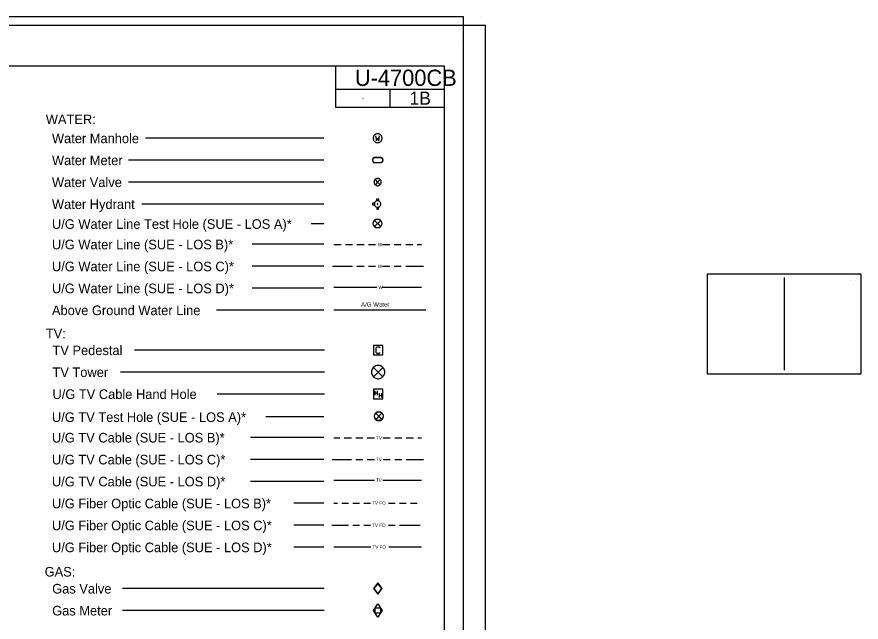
# Model space of a CAD drawing. Extents: x 811137 to 813186, y 647386 to 648494.
# Drawn here: x 812410 to 813186, y 647937 to 648494 of the extents above; entities that cross this region are included whole.
import ezdxf

# ---------------------------------------------------------------- set-up
doc = ezdxf.new("R2010")
doc.units = 0
for name, color, linetype in [('Default', 7, 'Continuous'), ('Exist Utilities TV Test Hole SUE LOS A CELL', 7, 'Continuous'), ('Exist Utilities Water Test Hole SUE LOS A CELL', 7, 'Continuous'), ('Sheet_Plan', 7, 'Continuous'), ('Sheet_Symbology', 7, 'Continuous'), ('Sheet_Title_Block_Text', 7, 'Continuous'), ('z - Construction', 7, 'Continuous')]:
    doc.layers.add(name, color=color, linetype=linetype)

msp = doc.modelspace()

# ---------------------------------------------------------------- linework, layer by layer
at = {"layer": 'Default'}
for p, q in [((812836.63, 648494.02), (812836.63, 648494.02)), ((812836.63, 648494.02), (812836.63, 648494.02)), ((812836.63, 648494.02), (812836.63, 648494.02)), ((812815.58, 648471.57), (812815.58, 648471.57)), ((812815.58, 648471.57), (812815.58, 648471.57)), ((812815.58, 648471.57), (812815.58, 648471.57))]:
    msp.add_line(p, q, dxfattribs=at)
msp.add_lwpolyline([(812820.63, 648494.02), (811136.63, 648494.02), (811136.63, 647394.02), (812820.63, 647394.02)], close=True, dxfattribs=at)
at = {"layer": 'Exist Utilities TV Test Hole SUE LOS A CELL'}
for points in [[(812745.62, 648129.54), (812739.92, 648123.83), (812742.77, 648126.69), (812739.92, 648129.54), (812745.62, 648123.83)], [(812739.92, 648129.54), (812742.77, 648126.69), (812745.62, 648129.54)], [(812745.62, 648123.83), (812742.77, 648126.69), (812739.92, 648123.83)]]:
    msp.add_lwpolyline(points, dxfattribs=at)
msp.add_circle((812742.77, 648126.69), 4.03, dxfattribs=at)
for start, end in [(45, 135), (225, 315)]:
    msp.add_arc((812742.77, 648126.69), 4.03, start, end, dxfattribs=at)
at = {"layer": 'Exist Utilities Water Test Hole SUE LOS A CELL'}
for points in [[(812744.47, 648306.86), (812738.77, 648301.15), (812741.62, 648304), (812738.77, 648306.86), (812744.47, 648301.15)], [(812738.77, 648306.86), (812741.62, 648304), (812744.47, 648306.86)], [(812744.47, 648301.15), (812741.62, 648304), (812738.77, 648301.15)]]:
    msp.add_lwpolyline(points, dxfattribs=at)
msp.add_circle((812741.62, 648304), 4.03, dxfattribs=at)
for start, end in [(45, 135), (225, 315)]:
    msp.add_arc((812741.62, 648304), 4.03, start, end, dxfattribs=at)
at = {"layer": 'Sheet_Plan'}
for p, q in [((812803.27, 648448.58), (811178.27, 648448.58)), ((812703.28, 648410.66), (812703.28, 648448.58)), ((812803.25, 647423.58), (812803.27, 648448.58)), ((812803.27, 648427.16), (812703.28, 648427.16)), ((812753.27, 648410.66), (812753.28, 648427.16)), ((812803.27, 648410.66), (812703.28, 648410.66))]:
    msp.add_line(p, q, dxfattribs=at)
msp.add_circle((812703.28, 648410.66), 0.06, dxfattribs=at)
at = {"layer": 'Sheet_Symbology'}
for p, q in [((812692.2, 648382.43), (812528.37, 648382.43)), ((812692.2, 648362.25), (812512.58, 648362.25)), ((812738.58, 648364.85), (812744.77, 648364.85)), ((812738.58, 648364.65), (812744.77, 648364.65)), ((812744.73, 648359.91), (812738.58, 648359.91)), ((812744.73, 648359.7), (812738.58, 648359.7)), ((812692.2, 648342.08), (812512.58, 648342.08)), ((812692.2, 648321.9), (812524.94, 648321.9)), ((812692.2, 648303.65), (812680.55, 648303.65)), ((812692.2, 648284.84), (812626.24, 648284.84)), ((812701.46, 648284.62), (812708.02, 648284.62)), ((812712.06, 648284.62), (812718.61, 648284.62)), ((812722.65, 648284.62), (812729.21, 648284.62)), ((812733.24, 648284.62), (812739.8, 648284.62)), ((812746.26, 648284.62), (812752.82, 648284.62)), ((812756.85, 648284.62), (812763.41, 648284.62)), ((812767.45, 648284.62), (812774, 648284.62)), ((812778.04, 648284.62), (812782.01, 648284.62)), ((812692.2, 648264.66), (812626.24, 648264.66)), ((812700.32, 648264.66), (812718.61, 648264.66)), ((812722.65, 648264.66), (812729.21, 648264.66)), ((812733.24, 648264.66), (812739.8, 648264.66)), ((812746.26, 648264.66), (812752.82, 648264.66)), ((812756.85, 648264.66), (812763.41, 648264.66)), ((812767.45, 648264.66), (812783.9, 648264.66)), ((812692.2, 648244.48), (812626.24, 648244.48)), ((812701.3, 648245.36), (812740.95, 648245.36)), ((812745.99, 648245.36), (812782.01, 648245.36)), ((812692.2, 648224.3), (812593.62, 648224.3)), ((812701.3, 648224.52), (812786.06, 648224.52)), ((812692.69, 648187.53), (812518.23, 648187.53)), ((812741.5, 648184.56), (812742.8, 648184.56)), ((812692.69, 648167.35), (812505.18, 648167.35)), ((812739.04, 648150.23), (812739.04, 648146.16)), ((812739.04, 648148.15), (812741.37, 648148.15)), ((812741.37, 648150.23), (812741.37, 648146.16)), ((812742.93, 648148.01), (812742.93, 648143.95)), ((812745.25, 648148.01), (812745.25, 648143.95)), ((812692.69, 648147.17), (812594.1, 648147.17)), ((812742.93, 648145.94), (812745.25, 648145.94)), ((812692.2, 648126.05), (812638.87, 648126.05)), ((812692.2, 648107.17), (812624.92, 648107.17)), ((812701.3, 648106.84), (812706.92, 648106.84)), ((812710.96, 648106.84), (812717.52, 648106.84)), ((812721.55, 648106.84), (812728.11, 648106.84)), ((812732.15, 648106.84), (812738.7, 648106.84)), ((812746.78, 648106.84), (812753.33, 648106.84)), ((812757.37, 648106.84), (812763.93, 648106.84)), ((812767.96, 648106.84), (812774.52, 648106.84)), ((812778.56, 648106.84), (812782.01, 648106.84)), ((812692.2, 648086.99), (812624.92, 648086.99)), ((812699.9, 648086.99), (812717.52, 648086.99)), ((812721.55, 648086.99), (812728.11, 648086.99)), ((812732.15, 648086.99), (812738.7, 648086.99)), ((812746.78, 648086.99), (812753.33, 648086.99)), ((812757.37, 648086.99), (812763.93, 648086.99)), ((812767.96, 648086.99), (812783.71, 648086.99)), ((812692.2, 648066.81), (812624.92, 648066.81)), ((812701.3, 648068.03), (812738.8, 648068.03)), ((812746.37, 648068.03), (812782.01, 648068.03)), ((812692.2, 648046.63), (812664.72, 648046.63)), ((812701.3, 648046.88), (812704.83, 648046.88)), ((812708.86, 648046.88), (812714.92, 648046.88)), ((812718.95, 648046.88), (812725.01, 648046.88)), ((812729.04, 648046.88), (812735.1, 648046.88)), ((812751.74, 648046.88), (812757.8, 648046.88)), ((812761.83, 648046.88), (812767.89, 648046.88)), ((812771.92, 648046.88), (812777.98, 648046.88)), ((812692.2, 648026.45), (812664.72, 648026.45)), ((812699.64, 648026.45), (812714.92, 648026.45)), ((812718.95, 648026.45), (812725.01, 648026.45)), ((812729.04, 648026.45), (812735.1, 648026.45)), ((812751.74, 648026.45), (812757.8, 648026.45)), ((812761.83, 648026.45), (812780.73, 648026.45)), ((812692.2, 648006.28), (812664.72, 648006.28)), ((812701.3, 648006.51), (812735.39, 648006.51)), ((812752.03, 648006.51), (812782.01, 648006.51)), ((812741.86, 647973.03), (812738.32, 647968.27)), ((812745.41, 647968.27), (812741.86, 647973.03)), ((812692.41, 647968.27), (812507.28, 647968.27)), ((812738.32, 647968.27), (812741.86, 647963.51)), ((812741.86, 647963.51), (812745.41, 647968.27)), ((812692.41, 647948.09), (812507.28, 647948.09))]:
    msp.add_line(p, q, dxfattribs=at)
for points in [[(812741.66, 648386.53), (812741.13, 648386.5), (812740.64, 648386.4), (812740.15, 648386.23), (812739.69, 648386.01), (812739.26, 648385.74), (812738.87, 648385.42), (812738.51, 648385.02), (812738.21, 648384.63), (812737.95, 648384.17), (812737.79, 648383.68), (812737.66, 648383.19), (812737.59, 648382.7), (812737.59, 648382.17), (812737.66, 648381.68), (812737.79, 648381.16), (812737.95, 648380.7), (812738.21, 648380.24), (812738.51, 648379.84), (812738.87, 648379.45), (812739.26, 648379.12), (812739.69, 648378.86), (812740.15, 648378.63), (812740.64, 648378.47), (812741.16, 648378.37), (812741.66, 648378.34), (812742.18, 648378.37), (812742.67, 648378.47), (812743.16, 648378.63), (812743.62, 648378.86), (812744.05, 648379.12), (812744.44, 648379.45), (812744.8, 648379.84), (812745.1, 648380.24), (812745.36, 648380.7), (812745.52, 648381.19), (812745.65, 648381.68), (812745.72, 648382.17), (812745.72, 648382.7), (812745.65, 648383.19), (812745.52, 648383.71), (812745.36, 648384.17), (812745.1, 648384.63), (812744.8, 648385.02), (812744.44, 648385.42), (812744.05, 648385.74), (812743.62, 648386.01), (812743.16, 648386.23), (812742.67, 648386.4), (812742.15, 648386.5), (812741.66, 648386.53)], [(812739.82, 648384.7), (812740.67, 648379.91), (812741.66, 648382.93), (812742.67, 648379.91), (812743.52, 648384.7)], [(812738.58, 648364.85), (812738.17, 648364.65), (812737.81, 648364.36), (812737.48, 648364), (812737.24, 648363.63), (812737.04, 648363.19), (812736.92, 648362.74), (812736.87, 648362.3), (812736.92, 648361.81), (812737.04, 648361.36), (812737.24, 648360.96), (812737.48, 648360.55), (812737.81, 648360.23), (812738.17, 648359.95), (812738.58, 648359.7)], [(812738.66, 648364.69), (812738.25, 648364.44), (812737.89, 648364.16), (812737.56, 648363.8), (812737.32, 648363.43), (812737.16, 648362.98), (812737.08, 648362.5), (812737.08, 648362.05), (812737.16, 648361.61), (812737.32, 648361.16), (812737.56, 648360.75), (812737.89, 648360.39), (812738.25, 648360.11), (812738.66, 648359.91)], [(812744.65, 648364.69), (812745.1, 648364.48), (812745.46, 648364.16), (812745.75, 648363.83), (812745.99, 648363.43), (812746.15, 648362.98), (812746.23, 648362.5), (812746.23, 648362.05), (812746.15, 648361.57), (812745.99, 648361.16), (812745.75, 648360.75), (812745.42, 648360.39), (812745.06, 648360.11), (812744.65, 648359.86)], [(812744.73, 648364.85), (812745.14, 648364.65), (812745.5, 648364.36), (812745.83, 648364), (812746.07, 648363.63), (812746.27, 648363.19), (812746.4, 648362.74), (812746.44, 648362.3), (812746.4, 648361.81), (812746.27, 648361.36), (812746.07, 648360.96), (812745.83, 648360.55), (812745.5, 648360.23), (812745.14, 648359.95), (812744.73, 648359.7)], [(812745.01, 648342.08), (812744.97, 648342.56), (812744.86, 648343.08), (812744.67, 648343.53), (812744.41, 648343.98), (812744.11, 648344.35), (812743.74, 648344.68), (812743.33, 648344.98), (812742.88, 648345.2), (812742.4, 648345.35), (812741.92, 648345.43), (812741.39, 648345.43), (812740.91, 648345.35), (812740.43, 648345.2), (812739.98, 648344.98), (812739.57, 648344.68), (812739.2, 648344.35), (812738.9, 648343.98), (812738.64, 648343.53), (812738.45, 648343.08), (812738.34, 648342.56), (812738.3, 648342.08), (812738.34, 648341.59), (812738.45, 648341.07), (812738.64, 648340.62), (812738.9, 648340.18), (812739.2, 648339.8), (812739.57, 648339.47), (812739.98, 648339.17), (812740.43, 648338.95), (812740.91, 648338.8), (812741.39, 648338.73), (812741.92, 648338.73), (812742.4, 648338.8), (812742.88, 648338.95), (812743.33, 648339.17), (812743.74, 648339.47), (812744.11, 648339.8), (812744.41, 648340.18), (812744.67, 648340.62), (812744.86, 648341.07), (812744.97, 648341.59), (812745.01, 648342.08)], [(812744.04, 648339.69), (812739.27, 648344.46), (812741.66, 648342.08), (812739.27, 648339.69), (812744.04, 648344.46)], [(812740.92, 648324.8), (812740.92, 648326.74), (812742.47, 648326.74), (812742.47, 648324.76)], [(812738.79, 648322.67), (812736.85, 648322.67), (812736.85, 648321.12), (812738.79, 648321.12)], [(812741.62, 648324.88), (812741.15, 648324.84), (812740.69, 648324.72), (812740.22, 648324.53), (812739.83, 648324.26), (812739.49, 648323.95), (812739.18, 648323.56), (812738.94, 648323.14), (812738.79, 648322.67), (812738.67, 648322.21), (812738.67, 648321.74), (812738.75, 648321.28), (812738.87, 648320.81), (812739.1, 648320.39), (812739.37, 648320), (812739.72, 648319.65), (812740.11, 648319.34), (812740.53, 648319.15), (812741, 648318.99), (812741.46, 648318.92), (812741.93, 648318.92), (812742.39, 648318.99), (812742.85, 648319.19), (812743.28, 648319.38), (812743.67, 648319.69), (812743.98, 648320.04), (812744.25, 648320.43), (812744.44, 648320.89), (812744.6, 648321.36), (812744.64, 648321.82), (812744.6, 648322.29), (812744.52, 648322.75), (812744.33, 648323.21), (812744.1, 648323.64), (812743.79, 648323.99), (812743.4, 648324.3), (812743.01, 648324.57), (812742.55, 648324.72), (812742.08, 648324.84), (812741.62, 648324.88)], [(812740.92, 648318.99), (812740.92, 648317.06), (812742.47, 648317.06), (812742.47, 648319.03)], [(812741.66, 648322.25), (812741.5, 648322.21), (812741.38, 648322.09), (812741.31, 648321.94), (812741.35, 648321.78), (812741.42, 648321.63), (812741.58, 648321.55), (812741.73, 648321.55), (812741.89, 648321.63), (812741.96, 648321.78), (812742, 648321.94), (812741.93, 648322.09), (812741.81, 648322.21), (812741.66, 648322.25)], [(812737.93, 648183.33), (812746.34, 648183.33), (812746.34, 648191.74), (812737.93, 648191.74), (812737.93, 648183.33)], [(812744.11, 648185.49), (812743.11, 648184.56), (812741.17, 648184.56), (812740.24, 648185.49), (812740.24, 648189.57), (812741.17, 648190.5), (812743.11, 648190.5), (812744.11, 648189.57)], [(812748.21, 648167.35), (812748.15, 648168.23), (812747.95, 648169.18), (812747.61, 648169.98), (812747.13, 648170.8), (812746.59, 648171.47), (812745.92, 648172.08), (812745.18, 648172.62), (812744.37, 648173.02), (812743.49, 648173.3), (812742.61, 648173.43), (812741.66, 648173.43), (812740.79, 648173.3), (812739.91, 648173.02), (812739.1, 648172.62), (812738.36, 648172.08), (812737.68, 648171.47), (812737.14, 648170.8), (812736.67, 648169.98), (812736.33, 648169.18), (812736.13, 648168.23), (812736.06, 648167.35), (812736.13, 648166.47), (812736.33, 648165.53), (812736.67, 648164.72), (812737.14, 648163.91), (812737.68, 648163.23), (812738.36, 648162.62), (812739.1, 648162.08), (812739.91, 648161.68), (812740.79, 648161.41), (812741.66, 648161.28), (812742.61, 648161.28), (812743.49, 648161.41), (812744.37, 648161.68), (812745.18, 648162.08), (812745.92, 648162.62), (812746.59, 648163.23), (812747.13, 648163.91), (812747.61, 648164.72), (812747.95, 648165.53), (812748.15, 648166.47), (812748.21, 648167.35)], [(812746.46, 648163.03), (812737.82, 648171.67), (812742.14, 648167.35), (812737.82, 648163.03), (812746.46, 648171.67)], [(812737.79, 648142.83), (812746.48, 648142.83), (812746.48, 648151.52), (812737.79, 648151.52), (812737.79, 648142.83)], [(812741.86, 647973.44), (812738.01, 647968.27), (812741.86, 647963.1), (812745.71, 647968.27), (812741.86, 647973.44)], [(812738.01, 647948.09), (812741.86, 647954.32), (812745.71, 647948.09), (812741.86, 647941.86), (812738.01, 647948.09)], [(812739.48, 647950.42), (812744.24, 647950.42), (812744.24, 647945.71), (812739.48, 647945.71), (812739.48, 647950.42)]]:
    msp.add_lwpolyline(points, dxfattribs=at)
at = {"layer": 'z - Construction'}
for p, q in [((812840.77, 648486.08), (811140.78, 648486.08)), ((812840.77, 647386.08), (812840.77, 648486.08)), ((813186.12, 648257.54), (813044.46, 648257.54)), ((813044.46, 648257.54), (813044.46, 648165.88)), ((813186.12, 648165.88), (813186.12, 648257.54)), ((813115.29, 648254.42), (813115.29, 648169)), ((813044.46, 648165.88), (813186.12, 648165.88))]:
    msp.add_line(p, q, dxfattribs=at)
for centre, radius in [((812753.28, 648437.87), 0.06), ((812728.28, 648418.91), 0.06), ((812778.27, 648418.91), 0.06), ((813176.75, 648251.95), 0.005), ((813178.83, 648253.53), 0.005), ((813180.92, 648251.95), 0.005)]:
    msp.add_circle(centre, radius, dxfattribs=at)

# ---------------------------------------------------------------- texts
at = {"layer": 'Sheet_Symbology'}
for s, height, p in [('WATER:', 8.828, (812436.67, 648395.39)), ('Water Manhole', 8.8282, (812442.29, 648377.86)), ('Water Meter', 8.8282, (812442.29, 648357.68)), ('Water Valve', 8.8282, (812442.29, 648337.5)), ('Water Hydrant', 8.8282, (812442.29, 648317.32)), ('U/G Water Line Test Hole (SUE - LOS A)*', 8.8282, (812442.29, 648299.07)), ('U/G Water Line (SUE - LOS B)*', 8.8282, (812442.29, 648280.26)), ('W', 3.03, (812741.92, 648283.1)), ('U/G Water Line (SUE - LOS C)*', 8.8282, (812442.29, 648260.08)), ('W', 3.03, (812741.92, 648263.14)), ('U/G Water Line (SUE - LOS D)*', 8.8282, (812442.29, 648239.9)), ('W', 3.03, (812742.36, 648243.85)), ('Above Ground Water Line', 8.8282, (812442.29, 648219.72)), ('A/G Water', 4.036, (812726.45, 648227.54)), ('TV:', 8.828, (812436.67, 648198.37)), ('TV Pedestal', 8.8282, (812442.77, 648182.95)), ('TV Tower', 8.828, (812442.77, 648162.77)), ('U/G TV Cable Hand Hole', 8.8282, (812442.77, 648142.6)), ('U/G TV Test Hole (SUE - LOS A)*', 8.8282, (812442.29, 648121.48)), ('U/G TV Cable (SUE - LOS B)*', 8.8282, (812442.29, 648102.59)), ('TV', 3.027, (812740.27, 648105.33)), ('U/G TV Cable (SUE - LOS C)*', 8.8282, (812442.29, 648082.41)), ('TV', 3.027, (812740.27, 648085.48)), ('U/G TV Cable (SUE - LOS D)*', 8.8282, (812442.29, 648062.23)), ('TV', 3.027, (812740.12, 648066.52)), ('U/G Fiber Optic Cable (SUE - LOS B)*', 8.8282, (812442.29, 648042.06)), ('TV FO', 3.027, (812736.66, 648045.36)), ('U/G Fiber Optic Cable (SUE - LOS C)*', 8.8282, (812442.29, 648021.88)), ('TV FO', 3.027, (812736.66, 648024.94)), ('U/G Fiber Optic Cable (SUE - LOS D)*', 8.8282, (812442.29, 648001.7)), ('TV FO', 3.027, (812736.95, 648005)), ('GAS:', 8.828, (812435.57, 647979.29)), ('Gas Valve', 8.828, (812442.5, 647963.69)), ('Gas Meter', 8.828, (812442.5, 647943.51))]:
    msp.add_text(s, height=height, dxfattribs=at).set_placement(p)
at = {"layer": 'Sheet_Title_Block_Text'}
for s, height, p in [('U-4700CB', 15, (812720.75, 648430.5)), ('1B', 12, (812771, 648413.24))]:
    msp.add_text(s, height=height, dxfattribs=at).set_placement(p)

doc.saveas('drawing.dxf')
